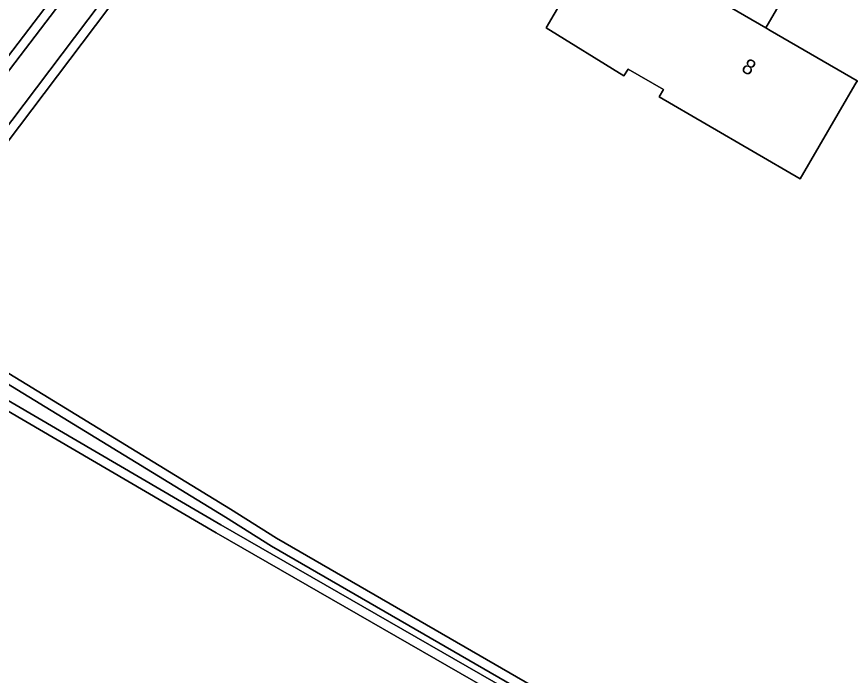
# Model space of a CAD drawing. Extents: x 156502 to 159075, y 384229 to 386100.
# Drawn here: x 157051.2 to 157106.1, y 385818.9 to 385862.3 of the extents above; entities that cross this region are included whole.
import ezdxf

# ---------------------------------------------------------------- set-up
doc = ezdxf.new("R2010")
doc.units = 0
for name, color, linetype in [('IMGEO_Erf', 7, 'Continuous'), ('IMGEO_Groenvoorziening', 7, 'Continuous'), ('IMGEO_Hek', 7, 'Continuous'), ('IMGEO_Oever', 7, 'Continuous'), ('IMGEO_Pand', 7, 'Continuous'), ('IMGEO_Pand_nummerreeks', 7, 'Continuous'), ('IMGEO_Voetpad_open', 7, 'Continuous'), ('IMGEO_Waterloop', 7, 'Continuous')]:
    doc.layers.add(name, color=color, linetype=linetype)

msp = doc.modelspace()

# ---------------------------------------------------------------- linework, layer by layer
at = {"layer": 'IMGEO_Erf'}
for points in [[(157106.562, 385858.084), (157102.808, 385851.646), (157093.53, 385857.04), (157093.801, 385857.507), (157091.477, 385858.867), (157091.192, 385858.41), (157086.085, 385861.587), (157093.153, 385873.673), (157098.324, 385870.649), (157094.927, 385864.842), (157100.545, 385861.579), (157101.95, 385864.014), (157102.227, 385863.854), (157105.698, 385869.85), (157105.837, 385870.09), (157092.904, 385877.624), (157087.856, 385869.139), (157069.928, 385879.631), (157069.688, 385879.771), (157062.244, 385869.451), (157047.224, 385849.55)], [(157042.786, 385843.67), (157065.314, 385829.887), (157068.346, 385827.983), (157173.435, 385767.228), (157172.677, 385766.006), (157064.372, 385828.327), (157041.356, 385841.775)]]:
    msp.add_lwpolyline(points, dxfattribs=at)
at = {"layer": 'IMGEO_Groenvoorziening'}
msp.add_lwpolyline([(157044.158, 385787.921), (157048.506, 385785.444), (157045.399, 385797.293), (157042.738, 385795.688), (157037.896, 385808.02), (157032.23, 385821.835), (157031.084, 385827.859), (157030.83, 385829.194), (157033.907, 385837.957), (157049.627, 385858.357), (157076.448, 385893.546), (157080.786, 385897.944), (157083.416, 385896.387), (157089.134, 385893.087), (157091.625, 385897.383), (157088.378, 385899.319)], dxfattribs=at)
at = {"layer": 'IMGEO_Hek'}
msp.add_lwpolyline([(157062.244, 385869.451), (157047.224, 385849.55)], dxfattribs=at)
at = {"layer": 'IMGEO_Oever'}
for points in [[(157076.448, 385893.546), (157049.627, 385858.357), (157033.907, 385837.957), (157030.83, 385829.194), (157031.084, 385827.859), (157032.23, 385821.835), (157037.896, 385808.02), (157042.738, 385795.688), (157045.399, 385797.293), (157034.848, 385824.224)], [(157036.041, 385834.964), (157036.588, 385835.458), (157041.356, 385841.775), (157064.372, 385828.327), (157172.677, 385766.006), (157173.435, 385767.228), (157068.346, 385827.983), (157065.314, 385829.887), (157042.786, 385843.67), (157047.224, 385849.55), (157062.244, 385869.451), (157069.688, 385879.771), (157078.432, 385891.893), (157077.479, 385892.687), (157076.448, 385893.546)], [(157050.121, 385857.979), (157076.549, 385892.652), (157077.081, 385892.209), (157077.588, 385891.786), (157069.183, 385880.135), (157061.743, 385869.82), (157046.727, 385849.925)], [(157042.409, 385843.171), (157064.986, 385829.358), (157068.025, 385827.45), (157172.568, 385767.011), (157172.466, 385766.846), (157064.684, 385828.865), (157041.733, 385842.275)]]:
    msp.add_lwpolyline(points, dxfattribs=at)
at = {"layer": 'IMGEO_Pand'}
msp.add_lwpolyline([(157100.836, 385861.41), (157100.545, 385861.579), (157094.927, 385864.842), (157098.324, 385870.649), (157093.153, 385873.673), (157086.085, 385861.587), (157091.192, 385858.41), (157091.477, 385858.867), (157093.801, 385857.507), (157093.53, 385857.04), (157102.808, 385851.646), (157106.562, 385858.084)], close=True, dxfattribs=at)
at = {"layer": 'IMGEO_Voetpad_open'}
msp.add_lwpolyline([(157116.16, 385883.109), (157114.16, 385884.269), (157111.651, 385879.994), (157106.141, 385870.607), (157105.837, 385870.09), (157105.698, 385869.85), (157102.227, 385863.854), (157101.95, 385864.014), (157100.545, 385861.579), (157100.836, 385861.41), (157106.562, 385858.084), (157112.648, 385854.542), (157123.992, 385847.954), (157134.715, 385841.68), (157146.045, 385835.121), (157155.595, 385829.52), (157159.85, 385827.054), (157183.031, 385813.57)], dxfattribs=at)
at = {"layer": 'IMGEO_Waterloop'}
for points in [[(157046.727, 385849.925), (157061.743, 385869.82), (157069.183, 385880.135), (157077.588, 385891.786), (157077.081, 385892.209), (157076.549, 385892.652), (157050.121, 385857.979)], [(157041.733, 385842.275), (157064.684, 385828.865), (157172.466, 385766.846), (157172.568, 385767.011), (157068.025, 385827.45), (157064.986, 385829.358), (157042.409, 385843.171)]]:
    msp.add_lwpolyline(points, dxfattribs=at)

# ---------------------------------------------------------------- texts
at = {"layer": 'IMGEO_Pand_nummerreeks'}
msp.add_text('8', height=1, rotation=329.8502, dxfattribs=at).set_placement((157098.865, 385858.762))

doc.saveas('drawing.dxf')
